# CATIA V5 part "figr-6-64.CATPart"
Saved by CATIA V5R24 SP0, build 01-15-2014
Part number: Part1
Bounding box of the stored display mesh (mm): x -50.648 to 50.648, y -72.183 to 72.183, z -40 to 40
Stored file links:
  D:\KAVITA\CATIA V5-6R2014 Project_ Kavita\CATIA V5-6R2014_partfiles\Partfiles\c06_catia_v5-6r2014_prt\figr-6-64.CATPart
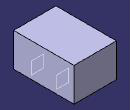
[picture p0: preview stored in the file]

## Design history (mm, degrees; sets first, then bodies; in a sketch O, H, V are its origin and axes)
Set1
  Plane1: type Offset, RefPlane face of Pad1, Offset -50, reversed
  Plane2: type Offset, RefPlane Plane1, Offset 53
Body1 (main body)
  Sketch1 on xy-plane, origin (0, 0, 0), H (1, 0, 0), V (0, 1, 0)
    line L1 (-50.6478, 72.1832) -> (50.6478, 72.1832)
    line L2 (50.6478, 72.1832) -> (50.6478, -72.1832)
    line L3 (50.6478, -72.1832) -> (-50.6478, -72.1832)
    line L4 (-50.6478, -72.1832) -> (-50.6478, 72.1832)
    axis line L5 (50.6478, -72.1832) -> (-50.6478, 72.1832)
    horizontal: L1 H, L3 H
    vertical: L2 V, L4 V
    midpoint: O L5
  Pad1: profile Sketch1, direction (0, 0, 1), length 40, mirrored extent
